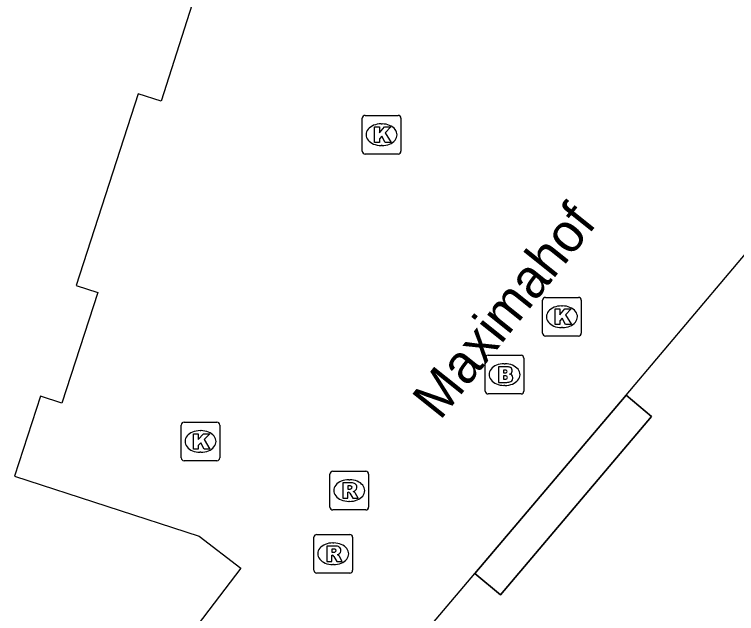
# Model space of a CAD drawing. Extents: x 161087 to 161922, y 382574 to 383873.
# Drawn here: x 161125.78 to 161144.48, y 383303.94 to 383319.44 of the extents above; entities that cross this region are included whole.
import ezdxf

# ---------------------------------------------------------------- set-up
doc = ezdxf.new("R2010")
doc.units = 0
for name, color, linetype in [('IMGEO_Brandkraan', 7, 'Continuous'), ('IMGEO_Kolk', 7, 'Continuous'), ('IMGEO_Openbare_ruimte_label', 7, 'Continuous'), ('IMGEO_Pand', 7, 'Continuous'), ('IMGEO_Pand_overbouw', 7, 'Continuous'), ('IMGEO_Rioolput', 7, 'Continuous'), ('IMGEO_Voetgangersgebied_open', 7, 'Continuous')]:
    doc.layers.add(name, color=color, linetype=linetype)

msp = doc.modelspace()

# ---------------------------------------------------------------- linework, layer by layer
at = {"layer": 'IMGEO_Brandkraan'}
for p, q in [((161137.973, 383309.698), (161137.973, 383310.55)), ((161138.048, 383310.624), (161138.9, 383310.624)), ((161138.974, 383310.55), (161138.974, 383309.698)), ((161138.461, 383310.404), (161138.486, 383310.404)), ((161138.484, 383309.844), (161138.459, 383309.844)), ((161138.9, 383309.624), (161138.048, 383309.624))]:
    msp.add_line(p, q, dxfattribs=at)
for points in [[(161137.973, 383309.698), (161137.973, 383310.55)], [(161138.048, 383310.624), (161138.9, 383310.624)], [(161138.974, 383310.55), (161138.974, 383309.698)], [(161138.321, 383310.324), (161138.321, 383309.924), (161138.534, 383309.924)], [(161138.552, 383310.324), (161138.321, 383310.324)], [(161138.5, 383310.243), (161138.446, 383310.243), (161138.446, 383310.167)], [(161138.446, 383310.167), (161138.499, 383310.167)], [(161138.508, 383310.091), (161138.446, 383310.091), (161138.446, 383310.01)], [(161138.446, 383310.01), (161138.508, 383310.01)], [(161138.9, 383309.624), (161138.048, 383309.624)]]:
    msp.add_lwpolyline(points, dxfattribs=at)
for centre, radius, start, end in [((161138.05, 383310.548), 0.0765, 91.552, 178.448), ((161138.05, 383310.548), 0.0765, 91.552, 178.448), ((161138.898, 383310.548), 0.0765, 1.552, 88.448), ((161138.898, 383310.548), 0.0765, 1.552, 88.448), ((161138.501, 383310.205), 0.0379, 267.8285, 90.9355), ((161138.556, 383310.179), 0.145, 59.4692, 91.5367), ((161138.581, 383310.226), 0.0922, 285.5137, 58.1501), ((161138.509, 383310.05), 0.0404, 269.8759, 90.5077), ((161138.586, 383310.034), 0.105, 301.3115, 78.989), ((161138.54, 383310.175), 0.251, 268.6676, 293.5347), ((161138.05, 383309.7), 0.0765, 181.552, 268.448), ((161138.05, 383309.7), 0.0765, 181.552, 268.448), ((161138.898, 383309.7), 0.0765, 271.552, 358.448), ((161138.898, 383309.7), 0.0765, 271.552, 358.448)]:
    msp.add_arc(centre, radius, start, end, dxfattribs=at)
for centre, major_axis, ratio, start_param, end_param in [((161138.46, 383310.124), (-0.387, 0.002), 0.722429, 4.712389, 7.853982), ((161138.485, 383310.124), (-0.39, 0.002), 0.717154, 1.570796, 4.712389)]:
    msp.add_ellipse(centre, major_axis=major_axis, ratio=ratio, start_param=start_param, end_param=end_param, dxfattribs=at)
at = {"layer": 'IMGEO_Kolk'}
for p, q in [((161134.79, 383315.906), (161134.79, 383316.758)), ((161134.865, 383316.832), (161135.717, 383316.832)), ((161135.791, 383316.758), (161135.791, 383315.906)), ((161135.278, 383316.612), (161135.303, 383316.612)), ((161135.301, 383316.052), (161135.276, 383316.052)), ((161135.717, 383315.832), (161134.865, 383315.832)), ((161139.46, 383311.196), (161139.46, 383312.048)), ((161139.535, 383312.122), (161140.387, 383312.122)), ((161140.461, 383312.048), (161140.461, 383311.196)), ((161139.948, 383311.902), (161139.973, 383311.902)), ((161139.971, 383311.342), (161139.946, 383311.342)), ((161140.387, 383311.122), (161139.535, 383311.122)), ((161130.176, 383308.894), (161131.028, 383308.894)), ((161130.101, 383307.968), (161130.101, 383308.82)), ((161130.589, 383308.674), (161130.614, 383308.674)), ((161131.102, 383308.82), (161131.102, 383307.968)), ((161130.612, 383308.114), (161130.587, 383308.114)), ((161131.028, 383307.894), (161130.176, 383307.894))]:
    msp.add_line(p, q, dxfattribs=at)
for points in [[(161134.79, 383315.906), (161134.79, 383316.758)], [(161134.865, 383316.832), (161135.717, 383316.832)], [(161135.791, 383316.758), (161135.791, 383315.906)], [(161135.111, 383316.532), (161135.234, 383316.532), (161135.234, 383316.381), (161135.364, 383316.532), (161135.528, 383316.532), (161135.382, 383316.381), (161135.535, 383316.132), (161135.383, 383316.132), (161135.298, 383316.296), (161135.234, 383316.229), (161135.234, 383316.132), (161135.111, 383316.132), (161135.111, 383316.532)], [(161135.717, 383315.832), (161134.865, 383315.832)], [(161139.46, 383311.196), (161139.46, 383312.048)], [(161139.535, 383312.122), (161140.387, 383312.122)], [(161140.461, 383312.048), (161140.461, 383311.196)], [(161139.781, 383311.822), (161139.904, 383311.822), (161139.904, 383311.671), (161140.034, 383311.822), (161140.198, 383311.822), (161140.052, 383311.671), (161140.205, 383311.422), (161140.053, 383311.422), (161139.968, 383311.586), (161139.904, 383311.519), (161139.904, 383311.422), (161139.781, 383311.422), (161139.781, 383311.822)], [(161140.387, 383311.122), (161139.535, 383311.122)], [(161130.176, 383308.894), (161131.028, 383308.894)], [(161130.101, 383307.968), (161130.101, 383308.82)], [(161131.102, 383308.82), (161131.102, 383307.968)], [(161130.422, 383308.594), (161130.545, 383308.594), (161130.545, 383308.443), (161130.675, 383308.594), (161130.839, 383308.594), (161130.693, 383308.443), (161130.846, 383308.194), (161130.694, 383308.194), (161130.609, 383308.358), (161130.545, 383308.291), (161130.545, 383308.194), (161130.422, 383308.194), (161130.422, 383308.594)], [(161131.028, 383307.894), (161130.176, 383307.894)]]:
    msp.add_lwpolyline(points, dxfattribs=at)
for centre, start, end in [((161134.867, 383316.756), 91.552, 178.448), ((161134.867, 383316.756), 91.552, 178.448), ((161135.715, 383316.756), 1.552, 88.448), ((161135.715, 383316.756), 1.552, 88.448), ((161134.867, 383315.908), 181.552, 268.448), ((161134.867, 383315.908), 181.552, 268.448), ((161135.715, 383315.908), 271.552, 358.448), ((161135.715, 383315.908), 271.552, 358.448), ((161139.537, 383312.046), 91.552, 178.448), ((161139.537, 383312.046), 91.552, 178.448), ((161140.385, 383312.046), 1.552, 88.448), ((161140.385, 383312.046), 1.552, 88.448), ((161139.537, 383311.198), 181.552, 268.448), ((161139.537, 383311.198), 181.552, 268.448), ((161140.385, 383311.198), 271.552, 358.448), ((161140.385, 383311.198), 271.552, 358.448), ((161130.178, 383308.818), 91.552, 178.448), ((161130.178, 383308.818), 91.552, 178.448), ((161131.026, 383308.818), 1.552, 88.448), ((161131.026, 383308.818), 1.552, 88.448), ((161130.178, 383307.97), 181.552, 268.448), ((161130.178, 383307.97), 181.552, 268.448), ((161131.026, 383307.97), 271.552, 358.448), ((161131.026, 383307.97), 271.552, 358.448)]:
    msp.add_arc(centre, 0.0765, start, end, dxfattribs=at)
for centre, major_axis, ratio, start_param, end_param in [((161135.277, 383316.332), (-0.387, 0.002), 0.722429, 4.712389, 7.853982), ((161135.302, 383316.332), (-0.39, 0.002), 0.717154, 1.570796, 4.712389), ((161139.947, 383311.622), (-0.387, 0.002), 0.722429, 4.712389, 7.853982), ((161139.972, 383311.622), (-0.39, 0.002), 0.717154, 1.570796, 4.712389), ((161130.588, 383308.394), (-0.387, 0.002), 0.722429, 4.712389, 7.853982), ((161130.613, 383308.394), (-0.39, 0.002), 0.717154, 1.570796, 4.712389)]:
    msp.add_ellipse(centre, major_axis=major_axis, ratio=ratio, start_param=start_param, end_param=end_param, dxfattribs=at)
at = {"layer": 'IMGEO_Pand'}
for points in [[(161130.514, 383320.127), (161129.583, 383317.196), (161128.987, 383317.389), (161127.383, 383312.427), (161127.939, 383312.247), (161127.014, 383309.387), (161126.455, 383309.568), (161125.784, 383307.492), (161130.564, 383305.947), (161131.65, 383305.119), (161127.864, 383300.155)], [(161141.622, 383309.593), (161149.625, 383319.064)], [(161141.622, 383309.593), (161142.279, 383309.038), (161138.369, 383304.424), (161137.707, 383304.978)], [(161131.326, 383297.432), (161135.611, 383302.499), (161137.707, 383304.978)]]:
    msp.add_lwpolyline(points, dxfattribs=at)
at = {"layer": 'IMGEO_Pand_overbouw'}
msp.add_lwpolyline([(161137.707, 383304.978), (161138.369, 383304.424), (161142.279, 383309.038), (161141.622, 383309.593)], close=True, dxfattribs=at)
at = {"layer": 'IMGEO_Rioolput'}
for p, q in [((161133.952, 383306.697), (161133.952, 383307.549)), ((161134.027, 383307.623), (161134.879, 383307.623)), ((161134.953, 383307.549), (161134.953, 383306.697)), ((161134.44, 383307.403), (161134.465, 383307.403)), ((161134.463, 383306.843), (161134.438, 383306.843)), ((161134.879, 383306.623), (161134.027, 383306.623)), ((161133.538, 383305.062), (161133.538, 383305.914)), ((161133.613, 383305.988), (161134.465, 383305.988)), ((161134.539, 383305.914), (161134.539, 383305.062)), ((161134.026, 383305.768), (161134.051, 383305.768)), ((161134.049, 383305.208), (161134.024, 383305.208)), ((161134.465, 383304.988), (161133.613, 383304.988))]:
    msp.add_line(p, q, dxfattribs=at)
for points in [[(161133.952, 383306.697), (161133.952, 383307.549)], [(161134.027, 383307.623), (161134.879, 383307.623)], [(161134.953, 383307.549), (161134.953, 383306.697)], [(161134.541, 383307.321), (161134.289, 383307.323), (161134.289, 383306.923)], [(161134.467, 383307.242), (161134.413, 383307.242), (161134.413, 383307.161)], [(161134.289, 383306.923), (161134.413, 383306.923), (161134.413, 383307.085), (161134.424, 383307.085)], [(161134.413, 383307.161), (161134.465, 383307.161)], [(161134.471, 383307.056), (161134.542, 383306.923), (161134.682, 383306.923), (161134.617, 383307.049)], [(161134.879, 383306.623), (161134.027, 383306.623)], [(161133.538, 383305.062), (161133.538, 383305.914)], [(161133.613, 383305.988), (161134.465, 383305.988)], [(161134.539, 383305.914), (161134.539, 383305.062)], [(161134.127, 383305.686), (161133.875, 383305.688), (161133.875, 383305.288)], [(161134.053, 383305.607), (161133.999, 383305.607), (161133.999, 383305.526)], [(161133.999, 383305.526), (161134.051, 383305.526)], [(161133.875, 383305.288), (161133.999, 383305.288), (161133.999, 383305.45), (161134.01, 383305.45)], [(161134.057, 383305.421), (161134.128, 383305.288), (161134.268, 383305.288), (161134.203, 383305.414)], [(161134.465, 383304.988), (161133.613, 383304.988)]]:
    msp.add_lwpolyline(points, dxfattribs=at)
for centre, radius, start, end in [((161134.029, 383307.547), 0.0765, 91.552, 178.448), ((161134.029, 383307.547), 0.0765, 91.552, 178.448), ((161134.877, 383307.547), 0.0765, 1.552, 88.448), ((161134.877, 383307.547), 0.0765, 1.552, 88.448), ((161134.473, 383307.146), 0.0964, 77.0061, 93.1865), ((161134.487, 383307.203), 0.0378, 276.6634, 79.6772), ((161134.54, 383307.211), 0.109, 350.3612, 89.416), ((161134.538, 383307.211), 0.112, 277.5842, 350.9817), ((161134.423, 383307.032), 0.0533, 26.0293, 88.6989), ((161134.449, 383307.35), 0.19, 274.7715, 282.9687), ((161134.522, 383306.996), 0.108, 29.5134, 73.7905), ((161134.029, 383306.699), 0.0765, 181.552, 268.448), ((161134.029, 383306.699), 0.0765, 181.552, 268.448), ((161134.877, 383306.699), 0.0765, 271.552, 358.448), ((161134.877, 383306.699), 0.0765, 271.552, 358.448), ((161133.615, 383305.912), 0.0765, 91.552, 178.448), ((161133.615, 383305.912), 0.0765, 91.552, 178.448), ((161134.463, 383305.912), 0.0765, 1.552, 88.448), ((161134.463, 383305.912), 0.0765, 1.552, 88.448), ((161134.126, 383305.576), 0.109, 350.3612, 89.416), ((161134.035, 383305.715), 0.19, 274.7715, 282.9687), ((161134.059, 383305.511), 0.0964, 77.0061, 93.1865), ((161134.073, 383305.568), 0.0378, 276.6634, 79.6772), ((161134.124, 383305.576), 0.112, 277.5842, 350.9817), ((161134.009, 383305.397), 0.0533, 26.0293, 88.6989), ((161134.108, 383305.361), 0.108, 29.5134, 73.7905), ((161133.615, 383305.064), 0.0765, 181.552, 268.448), ((161133.615, 383305.064), 0.0765, 181.552, 268.448), ((161134.463, 383305.064), 0.0765, 271.552, 358.448), ((161134.463, 383305.064), 0.0765, 271.552, 358.448)]:
    msp.add_arc(centre, radius, start, end, dxfattribs=at)
for centre, major_axis, ratio, start_param, end_param in [((161134.439, 383307.123), (-0.387, 0.002), 0.722429, 4.712389, 7.853982), ((161134.464, 383307.123), (-0.39, 0.002), 0.717154, 1.570796, 4.712389), ((161134.025, 383305.488), (-0.387, 0.002), 0.722429, 4.712389, 7.853982), ((161134.05, 383305.488), (-0.39, 0.002), 0.717154, 1.570796, 4.712389)]:
    msp.add_ellipse(centre, major_axis=major_axis, ratio=ratio, start_param=start_param, end_param=end_param, dxfattribs=at)
at = {"layer": 'IMGEO_Voetgangersgebied_open'}
msp.add_lwpolyline([(161137.707, 383304.978), (161141.622, 383309.593)], dxfattribs=at)

# ---------------------------------------------------------------- texts
at = {"layer": 'IMGEO_Openbare_ruimte_label'}
msp.add_text('Maximahof', height=1, rotation=51.376, dxfattribs=at).set_placement((161136.804, 383308.918))

doc.saveas('drawing.dxf')
